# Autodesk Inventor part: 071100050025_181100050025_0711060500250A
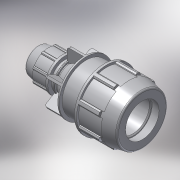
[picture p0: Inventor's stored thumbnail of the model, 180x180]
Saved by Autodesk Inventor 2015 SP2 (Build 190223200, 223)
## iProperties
Created: 2017-02
Part Number: 071100050025_181100050025_0711060500250A
Material: PVC-Piping
Description: PLASSON REDUCING COUPLER 50-25
Document SubType Name: Modeling
Designer: KIM
Mass: 92.6774 g
Surface Area: 199.44 cm^2
Volume: 66.1981 cm^3
Density: 1.4 g/cm^3
Appearance: Smooth - White
Author: KIM
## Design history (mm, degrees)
derived "07110.ipt"
feature "Solid1::07110.ipt"
tag "TaggingFeature1"
body "Solid1"
other parameters: "d4" = 14.66667, "d5" = 25.14286, "d7" = 96, "d9" = 25.14286, "d11" = 2.51429, "d12" = 76.8, "d13" = 120 deg, "d14" = 75, "d15" = 12 deg, "d16" = 86.4, "d18" = 2.5, "d19" = 35 deg, "d20" = 17.5 deg, "d21" = 89.28, "d23" = 0, "d25" = 360 deg, "d27" = 1.92, "d42" = 38.72, "d46" = 1.5, "d51" = 176, "d52" = 25.14286, "d53" = 12 deg, "d54" = 93, "d56" = 37.5, "d57" = 25, "d58" = 45, "d59" = 22.5, "d60" = 48.6, "d61" = 43.2, "d62" = 17.6, "d63" = 28.16, "d64" = 120 deg, "d65" = 54, "d68" = 12.57143, "d74" = 50.22, "d75" = 35 deg, "d76" = 17.5 deg, "d78" = 0, "d80" = 360 deg, "d85" = 1.08, "d88" = 0.5, "d93" = 58, "d94" = 67.2, "d97" = 3.28333, "d98" = 3.6, "d99" = 0, "d100" = 3.84, "d102" = 360 deg, "d104" = 2, "d106" = 0, "d107" = 3.6, "d108" = 0, "d109" = 3.6, "d110" = 0, "E_" = 96, "H_" = 176, "l_" = 93, "d_1" = 25, "E_1" = 54, "l_1" = 58, "d96" = 9.85
